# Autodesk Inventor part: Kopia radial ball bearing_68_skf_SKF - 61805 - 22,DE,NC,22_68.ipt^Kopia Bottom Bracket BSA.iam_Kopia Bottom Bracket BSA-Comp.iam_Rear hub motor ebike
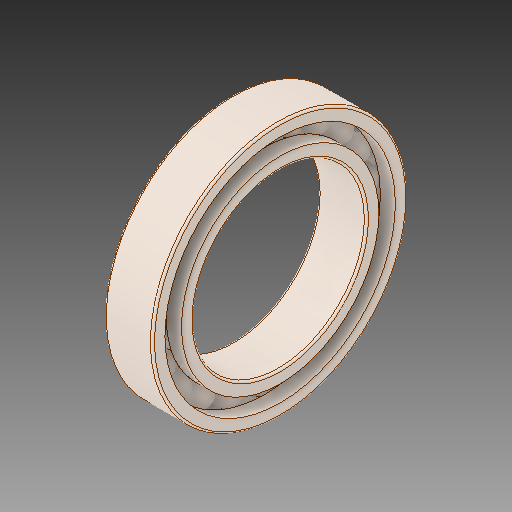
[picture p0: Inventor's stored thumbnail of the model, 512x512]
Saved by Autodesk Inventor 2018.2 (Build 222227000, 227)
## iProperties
Created: 2017-11
Part Number: Kopia radial ball bearing_68_skf_SKF - 61805 - 22,DE,NC,22_68.ipt^Kopia Bottom Bracket BSA.iam_Kopia Bottom Bracket BSA-Comp.iam_Rear hub motor ebike
Material: Ogólny
Document SubType Name: Modeling
Designer: Tomasz
Density: 1 g/cm^3
Appearance: Domyślna
Author: Tomasz
Sending System: SolidWorks 2017
Last Author: Tomasz
Last Saved: 2017-11-19
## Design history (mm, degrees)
feature "radial ball bearing_68_skf_SKF - 61805 - 22,DE,NC,22_68.ipt"
node "Bryła1"
